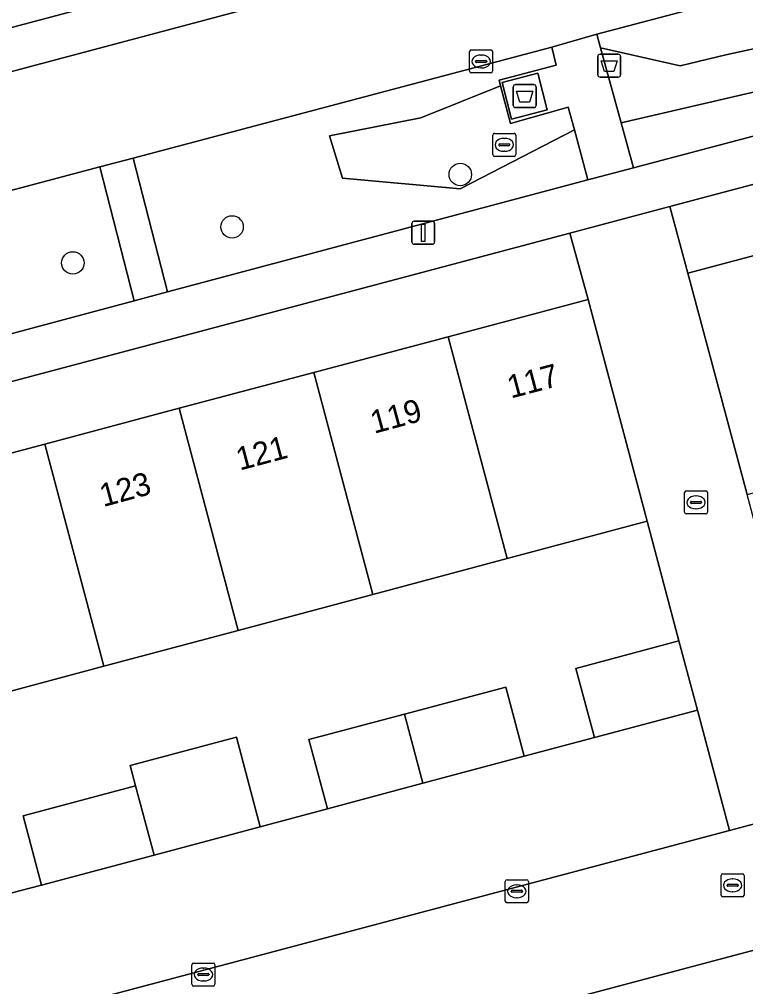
# Model space of a CAD drawing. Extents: x 162542 to 163147, y 380779 to 381521.
# Drawn here: x 162829.86 to 162861.43, y 381110.8 to 381152.86 of the extents above; entities that cross this region are included whole.
import ezdxf

# ---------------------------------------------------------------- set-up
doc = ezdxf.new("R2010")
doc.units = 0
for name, color, linetype in [('IMGEO_Afval_apart_plaats', 7, 'Continuous'), ('IMGEO_Afvalbak', 7, 'Continuous'), ('IMGEO_Boom', 7, 'Continuous'), ('IMGEO_Erf', 7, 'Continuous'), ('IMGEO_Groenvoorziening', 7, 'Continuous'), ('IMGEO_Kolk', 7, 'Continuous'), ('IMGEO_Lichtmast', 7, 'Continuous'), ('IMGEO_Muur', 7, 'Continuous'), ('IMGEO_Pand', 7, 'Continuous'), ('IMGEO_Pand_nummerreeks', 7, 'Continuous'), ('IMGEO_Parkeervlak_open', 7, 'Continuous'), ('IMGEO_Rijbaan_lokaal_open', 7, 'Continuous'), ('IMGEO_Rioolput', 7, 'Continuous'), ('IMGEO_Voetpad_gesloten', 7, 'Continuous'), ('IMGEO_Voetpad_open', 7, 'Continuous')]:
    doc.layers.add(name, color=color, linetype=linetype)

msp = doc.modelspace()

# ---------------------------------------------------------------- linework, layer by layer
at = {"layer": 'IMGEO_Afval_apart_plaats'}
for p, q in [((162851.333, 381149.125), (162851.333, 381149.925)), ((162851.333, 381149.925), (162851.333, 381149.125)), ((162851.433, 381150.025), (162852.223, 381150.025)), ((162852.223, 381150.025), (162851.433, 381150.025)), ((162852.323, 381149.925), (162852.323, 381149.125)), ((162852.323, 381149.125), (162852.323, 381149.925)), ((162852.223, 381149.025), (162851.433, 381149.025)), ((162851.433, 381149.025), (162852.223, 381149.025))]:
    msp.add_line(p, q, dxfattribs=at)
msp.add_lwpolyline([(162851.476, 381149.739), (162852.18, 381149.739), (162852.031, 381149.269), (162851.625, 381149.269), (162851.476, 381149.739)], dxfattribs=at)
for centre, start, end in [((162851.433, 381149.925), 90, 180), ((162851.433, 381149.925), 90, 180), ((162852.223, 381149.925), 0, 90), ((162852.223, 381149.925), 360, 90), ((162851.433, 381149.125), 180, 270), ((162851.433, 381149.125), 180, 270), ((162852.223, 381149.125), 270, 0), ((162852.223, 381149.125), 270, 0)]:
    msp.add_arc(centre, 0.1, start, end, dxfattribs=at)
at = {"layer": 'IMGEO_Afvalbak'}
for p, q in [((162855.006, 381150.45), (162855.006, 381151.25)), ((162855.006, 381151.25), (162855.006, 381150.45)), ((162855.106, 381151.35), (162855.896, 381151.35)), ((162855.896, 381151.35), (162855.106, 381151.35)), ((162855.996, 381151.25), (162855.996, 381150.45)), ((162855.996, 381150.45), (162855.996, 381151.25)), ((162855.896, 381150.35), (162855.106, 381150.35)), ((162855.106, 381150.35), (162855.896, 381150.35))]:
    msp.add_line(p, q, dxfattribs=at)
msp.add_lwpolyline([(162855.149, 381151.064), (162855.853, 381151.064), (162855.704, 381150.594), (162855.298, 381150.594), (162855.149, 381151.064)], dxfattribs=at)
for centre, start, end in [((162855.106, 381151.25), 90, 180), ((162855.106, 381151.25), 90, 180), ((162855.896, 381151.25), 0, 90), ((162855.896, 381151.25), 360, 90), ((162855.106, 381150.45), 180, 270), ((162855.106, 381150.45), 180, 270), ((162855.896, 381150.45), 270, 0), ((162855.896, 381150.45), 270, 0)]:
    msp.add_arc(centre, 0.1, start, end, dxfattribs=at)
at = {"layer": 'IMGEO_Boom'}
for centre in [(162849.03, 381146.117), (162839.107, 381143.836), (162832.187, 381142.27)]:
    msp.add_circle(centre, 0.489, dxfattribs=at)
at = {"layer": 'IMGEO_Erf'}
msp.add_lwpolyline([(162828.954, 381114.718), (162829.869, 381114.962), (162830.825, 381115.217), (162830.021, 381118.231), (162834.913, 381119.537), (162834.68, 381120.413), (162839.296, 381121.641), (162840.329, 381117.753), (162843.252, 381118.534), (162842.449, 381121.547), (162846.604, 381122.654), (162851.006, 381123.825), (162851.806, 381120.816), (162854.859, 381121.631), (162854.053, 381124.639), (162858.533, 381125.84), (162857.156, 381131.038), (162851.067, 381129.413), (162845.222, 381127.852), (162839.378, 381126.292), (162833.532, 381124.732), (162827.687, 381123.171)], dxfattribs=at)
at = {"layer": 'IMGEO_Groenvoorziening'}
for points in [[(162873.192, 381157.033), (162854.959, 381152.215), (162855.121, 381151.63), (162858.584, 381150.843), (162860.575, 381151.323), (162862.708, 381151.781), (162863.421, 381151.008), (162863.083, 381150.009), (162856.023, 381148.37), (162856.566, 381146.408), (162874.69, 381151.205)], [(162850.779, 381149.971), (162850.713, 381150.223), (162853.196, 381150.874), (162853.012, 381151.656), (162834.806, 381146.828), (162836.301, 381141.008), (162854.578, 381145.881), (162853.992, 381148.056), (162849.02, 381145.493), (162843.909, 381145.959), (162843.343, 381147.801), (162847.316, 381148.586)], [(162855.121, 381151.63), (162856.023, 381148.37), (162863.083, 381150.009), (162863.421, 381151.008), (162862.708, 381151.781), (162860.575, 381151.323), (162858.584, 381150.843)], [(162853.992, 381148.056), (162853.726, 381149.042), (162851.208, 381148.342), (162850.779, 381149.971), (162847.316, 381148.586), (162843.343, 381147.801), (162843.909, 381145.959), (162849.02, 381145.493)], [(162823.259, 381143.767), (162824.718, 381137.919), (162827.907, 381138.769), (162834.855, 381140.622), (162833.356, 381146.444)]]:
    msp.add_lwpolyline(points, close=True, dxfattribs=at)
at = {"layer": 'IMGEO_Kolk'}
for p, q in [((162849.509, 381151.533), (162850.361, 381151.533)), ((162849.434, 381150.607), (162849.434, 381151.459)), ((162849.922, 381151.313), (162849.947, 381151.313)), ((162850.435, 381151.459), (162850.435, 381150.607)), ((162849.693, 381151.027), (162849.693, 381151.039)), ((162850.131, 381150.99), (162849.733, 381150.99)), ((162849.736, 381151.076), (162850.134, 381151.076)), ((162849.945, 381150.753), (162849.92, 381150.753)), ((162850.177, 381151.039), (162850.177, 381151.027)), ((162850.361, 381150.533), (162849.509, 381150.533)), ((162858.777, 381131.431), (162858.777, 381132.283)), ((162858.852, 381132.357), (162859.704, 381132.357)), ((162859.778, 381132.283), (162859.778, 381131.431)), ((162859.036, 381131.851), (162859.036, 381131.863)), ((162859.474, 381131.814), (162859.076, 381131.814)), ((162859.079, 381131.9), (162859.477, 381131.9)), ((162859.265, 381132.137), (162859.29, 381132.137)), ((162859.52, 381131.863), (162859.52, 381131.851)), ((162859.704, 381131.357), (162858.852, 381131.357)), ((162859.288, 381131.577), (162859.263, 381131.577)), ((162850.987, 381114.519), (162850.987, 381115.371)), ((162851.062, 381115.445), (162851.914, 381115.445)), ((162851.988, 381115.371), (162851.988, 381114.519)), ((162851.246, 381114.939), (162851.246, 381114.951)), ((162851.289, 381114.988), (162851.687, 381114.988)), ((162851.475, 381115.225), (162851.5, 381115.225)), ((162851.73, 381114.951), (162851.73, 381114.939)), ((162851.684, 381114.902), (162851.286, 381114.902)), ((162851.498, 381114.665), (162851.473, 381114.665)), ((162851.914, 381114.445), (162851.062, 381114.445)), ((162837.363, 381110.899), (162837.363, 381111.751)), ((162837.438, 381111.825), (162838.29, 381111.825)), ((162837.851, 381111.605), (162837.876, 381111.605)), ((162838.364, 381111.751), (162838.364, 381110.899)), ((162837.622, 381111.319), (162837.622, 381111.331)), ((162838.06, 381111.282), (162837.662, 381111.282)), ((162837.665, 381111.368), (162838.063, 381111.368)), ((162838.106, 381111.331), (162838.106, 381111.319)), ((162838.29, 381110.825), (162837.438, 381110.825)), ((162837.874, 381111.045), (162837.849, 381111.045))]:
    msp.add_line(p, q, dxfattribs=at)
for points in [[(162849.509, 381151.533), (162850.361, 381151.533)], [(162849.434, 381150.607), (162849.434, 381151.459)], [(162850.435, 381151.459), (162850.435, 381150.607)], [(162850.361, 381150.533), (162849.509, 381150.533)], [(162858.777, 381131.431), (162858.777, 381132.283)], [(162858.852, 381132.357), (162859.704, 381132.357)], [(162859.778, 381132.283), (162859.778, 381131.431)], [(162859.704, 381131.357), (162858.852, 381131.357)], [(162850.987, 381114.519), (162850.987, 381115.371)], [(162851.062, 381115.445), (162851.914, 381115.445)], [(162851.988, 381115.371), (162851.988, 381114.519)], [(162851.914, 381114.445), (162851.062, 381114.445)], [(162837.363, 381110.899), (162837.363, 381111.751)], [(162837.438, 381111.825), (162838.29, 381111.825)], [(162838.364, 381111.751), (162838.364, 381110.899)], [(162838.29, 381110.825), (162837.438, 381110.825)]]:
    msp.add_lwpolyline(points, dxfattribs=at)
for centre, radius, start, end in [((162849.511, 381151.457), 0.0765, 91.552, 178.448), ((162849.511, 381151.457), 0.0765, 91.552, 178.448), ((162850.359, 381151.457), 0.0765, 1.552, 88.448), ((162850.359, 381151.457), 0.0765, 1.552, 88.448), ((162849.733, 381151.036), 0.0403, 85.8775, 175.7526), ((162849.73, 381151.026), 0.0366, 178.938, 274.7102), ((162850.134, 381151.033), 0.043, 264.8664, 352.4533), ((162850.138, 381151.038), 0.0386, 1.7309, 96.639), ((162849.511, 381150.609), 0.0765, 181.552, 268.448), ((162849.511, 381150.609), 0.0765, 181.552, 268.448), ((162850.359, 381150.609), 0.0765, 271.552, 358.448), ((162850.359, 381150.609), 0.0765, 271.552, 358.448), ((162858.854, 381132.281), 0.0765, 91.552, 178.448), ((162858.854, 381132.281), 0.0765, 91.552, 178.448), ((162859.702, 381132.281), 0.0765, 1.552, 88.448), ((162859.702, 381132.281), 0.0765, 1.552, 88.448), ((162859.076, 381131.86), 0.0403, 85.8775, 175.7526), ((162859.073, 381131.85), 0.0366, 178.938, 274.7102), ((162859.477, 381131.857), 0.043, 264.8664, 352.4533), ((162859.481, 381131.862), 0.0386, 1.7309, 96.639), ((162858.854, 381131.433), 0.0765, 181.552, 268.448), ((162858.854, 381131.433), 0.0765, 181.552, 268.448), ((162859.702, 381131.433), 0.0765, 271.552, 358.448), ((162859.702, 381131.433), 0.0765, 271.552, 358.448), ((162851.064, 381115.369), 0.0765, 91.552, 178.448), ((162851.064, 381115.369), 0.0765, 91.552, 178.448), ((162851.912, 381115.369), 0.0765, 1.552, 88.448), ((162851.912, 381115.369), 0.0765, 1.552, 88.448), ((162851.286, 381114.948), 0.0403, 85.8775, 175.7526), ((162851.283, 381114.938), 0.0366, 178.938, 274.7102), ((162851.687, 381114.945), 0.043, 264.8664, 352.4533), ((162851.691, 381114.95), 0.0386, 1.7309, 96.639), ((162851.064, 381114.521), 0.0765, 181.552, 268.448), ((162851.064, 381114.521), 0.0765, 181.552, 268.448), ((162851.912, 381114.521), 0.0765, 271.552, 358.448), ((162851.912, 381114.521), 0.0765, 271.552, 358.448), ((162837.44, 381111.749), 0.0765, 91.552, 178.448), ((162837.44, 381111.749), 0.0765, 91.552, 178.448), ((162838.288, 381111.749), 0.0765, 1.552, 88.448), ((162838.288, 381111.749), 0.0765, 1.552, 88.448), ((162837.662, 381111.328), 0.0403, 85.8775, 175.7526), ((162837.659, 381111.318), 0.0366, 178.938, 274.7102), ((162838.063, 381111.325), 0.043, 264.8664, 352.4533), ((162838.067, 381111.33), 0.0386, 1.7309, 96.639), ((162837.44, 381110.901), 0.0765, 181.552, 268.448), ((162837.44, 381110.901), 0.0765, 181.552, 268.448), ((162838.288, 381110.901), 0.0765, 271.552, 358.448), ((162838.288, 381110.901), 0.0765, 271.552, 358.448)]:
    msp.add_arc(centre, radius, start, end, dxfattribs=at)
for centre, major_axis, ratio, start_param, end_param in [((162849.921, 381151.033), (-0.387, 0.002), 0.722429, 4.712389, 7.853982), ((162849.946, 381151.033), (-0.39, 0.002), 0.717154, 1.570796, 4.712389), ((162859.264, 381131.857), (-0.387, 0.002), 0.722429, 4.712389, 7.853982), ((162859.289, 381131.857), (-0.39, 0.002), 0.717154, 1.570796, 4.712389), ((162851.474, 381114.945), (-0.387, 0.002), 0.722429, 4.712389, 7.853982), ((162851.499, 381114.945), (-0.39, 0.002), 0.717154, 1.570796, 4.712389), ((162837.85, 381111.325), (-0.387, 0.002), 0.722429, 4.712389, 7.853982), ((162837.875, 381111.325), (-0.39, 0.002), 0.717154, 1.570796, 4.712389)]:
    msp.add_ellipse(centre, major_axis=major_axis, ratio=ratio, start_param=start_param, end_param=end_param, dxfattribs=at)
at = {"layer": 'IMGEO_Lichtmast'}
for p, q in [((162846.925, 381143.181), (162846.925, 381143.981)), ((162846.925, 381143.981), (162846.925, 381143.181)), ((162847.025, 381144.081), (162847.815, 381144.081)), ((162847.815, 381144.081), (162847.025, 381144.081)), ((162847.915, 381143.981), (162847.915, 381143.181)), ((162847.915, 381143.181), (162847.915, 381143.981)), ((162847.815, 381143.081), (162847.025, 381143.081)), ((162847.025, 381143.081), (162847.815, 381143.081))]:
    msp.add_line(p, q, dxfattribs=at)
msp.add_lwpolyline([(162847.345, 381143.956), (162847.495, 381143.956), (162847.495, 381143.206), (162847.345, 381143.206), (162847.345, 381143.956)], dxfattribs=at)
for centre, start, end in [((162847.025, 381143.981), 90, 180), ((162847.025, 381143.981), 90, 180), ((162847.815, 381143.981), 0, 90), ((162847.815, 381143.981), 360, 90), ((162847.025, 381143.181), 180, 270), ((162847.025, 381143.181), 180, 270), ((162847.815, 381143.181), 270, 0), ((162847.815, 381143.181), 270, 0)]:
    msp.add_arc(centre, 0.1, start, end, dxfattribs=at)
at = {"layer": 'IMGEO_Muur'}
msp.add_lwpolyline([(162857.156, 381131.038), (162858.533, 381125.84)], dxfattribs=at)
at = {"layer": 'IMGEO_Pand'}
for points in [[(162865.183, 381143.493), (162858.926, 381141.83), (162861.5, 381132.198), (162867.747, 381133.851)], [(162851.067, 381129.413), (162857.156, 381131.038), (162854.582, 381140.682), (162848.502, 381139.062)], [(162845.222, 381127.852), (162851.067, 381129.413), (162848.502, 381139.062), (162842.656, 381137.506)], [(162845.222, 381127.852), (162842.656, 381137.506), (162836.811, 381135.949), (162839.378, 381126.292)], [(162830.964, 381134.392), (162833.532, 381124.732), (162839.378, 381126.292), (162836.811, 381135.949)], [(162825.118, 381132.835), (162827.687, 381123.171), (162833.532, 381124.732), (162830.964, 381134.392)], [(162858.533, 381125.84), (162854.053, 381124.639), (162854.859, 381121.631), (162859.337, 381122.826)], [(162851.006, 381123.825), (162846.604, 381122.654), (162847.405, 381119.642), (162851.806, 381120.816)], [(162846.604, 381122.654), (162842.449, 381121.547), (162843.252, 381118.534), (162847.405, 381119.642)], [(162834.913, 381119.537), (162835.715, 381116.522), (162840.329, 381117.753), (162839.296, 381121.641), (162834.68, 381120.413)], [(162834.913, 381119.537), (162830.021, 381118.231), (162830.825, 381115.217), (162835.715, 381116.522)]]:
    msp.add_lwpolyline(points, close=True, dxfattribs=at)
at = {"layer": 'IMGEO_Parkeervlak_open'}
for points in [[(162750.234, 381131.33), (162666.499, 381109.073), (162666.934, 381107.34), (162774.201, 381135.871), (162796.063, 381141.696), (162882.877, 381164.808), (162901.876, 381169.92), (162904.167, 381170.544), (162903.648, 381172.331), (162882.303, 381166.521), (162850.91, 381158.201), (162843.113, 381156.134), (162825.633, 381151.487), (162819.826, 381149.913), (162790.747, 381142.166), (162781.519, 381139.707), (162755.957, 381132.897)], [(162860.735, 381117.589), (162859.337, 381122.826), (162854.859, 381121.631), (162851.806, 381120.816), (162847.405, 381119.642), (162843.252, 381118.534), (162840.329, 381117.753), (162835.715, 381116.522), (162830.825, 381115.217), (162829.869, 381114.962), (162828.954, 381114.718), (162824.567, 381113.548), (162825.307, 381110.691), (162824.579, 381110.496), (162813.513, 381107.551), (162801.688, 381104.403), (162802.147, 381102.023)]]:
    msp.add_lwpolyline(points, close=True, dxfattribs=at)
at = {"layer": 'IMGEO_Rijbaan_lokaal_open'}
for points in [[(162854.959, 381152.215), (162873.192, 381157.033), (162874.356, 381157.34), (162885.803, 381160.365), (162885.815, 381160.368), (162895.148, 381162.891), (162896.342, 381163.214), (162903.106, 381165.042), (162901.876, 381169.92), (162882.877, 381164.808), (162796.063, 381141.696), (162797.369, 381136.894), (162804.174, 381138.709), (162806.152, 381139.231), (162816.765, 381142.045), (162822.073, 381143.452), (162823.259, 381143.767), (162833.356, 381146.444), (162834.806, 381146.828), (162853.012, 381151.656)], [(162901.595, 381122.971), (162901.741, 381122.714), (162904.267, 381123.387), (162904.26, 381123.431), (162912.087, 381125.607), (162919.026, 381127.451), (162917.722, 381132.729), (162865.087, 381118.745), (162860.735, 381117.589), (162802.147, 381102.023), (162803.453, 381096.881), (162812.174, 381099.193), (162820.968, 381101.532), (162820.992, 381101.538)]]:
    msp.add_lwpolyline(points, close=True, dxfattribs=at)
at = {"layer": 'IMGEO_Rioolput'}
for p, q in [((162850.442, 381146.981), (162850.442, 381147.833)), ((162850.517, 381147.907), (162851.369, 381147.907)), ((162851.443, 381147.833), (162851.443, 381146.981)), ((162850.701, 381147.401), (162850.701, 381147.413)), ((162851.139, 381147.364), (162850.741, 381147.364)), ((162850.744, 381147.45), (162851.142, 381147.45)), ((162850.93, 381147.687), (162850.955, 381147.687)), ((162851.185, 381147.413), (162851.185, 381147.401)), ((162851.369, 381146.907), (162850.517, 381146.907)), ((162850.953, 381147.127), (162850.928, 381147.127)), ((162860.368, 381114.779), (162860.368, 381115.631)), ((162860.443, 381115.705), (162861.295, 381115.705)), ((162860.856, 381115.485), (162860.881, 381115.485)), ((162861.369, 381115.631), (162861.369, 381114.779)), ((162860.627, 381115.199), (162860.627, 381115.211)), ((162861.065, 381115.162), (162860.667, 381115.162)), ((162860.67, 381115.248), (162861.068, 381115.248)), ((162860.879, 381114.925), (162860.854, 381114.925)), ((162861.111, 381115.211), (162861.111, 381115.199)), ((162861.295, 381114.705), (162860.443, 381114.705))]:
    msp.add_line(p, q, dxfattribs=at)
for points in [[(162850.442, 381146.981), (162850.442, 381147.833)], [(162850.517, 381147.907), (162851.369, 381147.907)], [(162851.443, 381147.833), (162851.443, 381146.981)], [(162851.369, 381146.907), (162850.517, 381146.907)], [(162860.368, 381114.779), (162860.368, 381115.631)], [(162860.443, 381115.705), (162861.295, 381115.705)], [(162861.369, 381115.631), (162861.369, 381114.779)], [(162861.295, 381114.705), (162860.443, 381114.705)]]:
    msp.add_lwpolyline(points, dxfattribs=at)
for centre, radius, start, end in [((162850.519, 381147.831), 0.0765, 91.552, 178.448), ((162850.519, 381147.831), 0.0765, 91.552, 178.448), ((162851.367, 381147.831), 0.0765, 1.552, 88.448), ((162851.367, 381147.831), 0.0765, 1.552, 88.448), ((162850.741, 381147.41), 0.0403, 85.8775, 175.7526), ((162850.738, 381147.4), 0.0366, 178.938, 274.7102), ((162851.142, 381147.407), 0.043, 264.8664, 352.4533), ((162851.146, 381147.412), 0.0386, 1.7309, 96.639), ((162850.519, 381146.983), 0.0765, 181.552, 268.448), ((162850.519, 381146.983), 0.0765, 181.552, 268.448), ((162851.367, 381146.983), 0.0765, 271.552, 358.448), ((162851.367, 381146.983), 0.0765, 271.552, 358.448), ((162860.445, 381115.629), 0.0765, 91.552, 178.448), ((162860.445, 381115.629), 0.0765, 91.552, 178.448), ((162861.293, 381115.629), 0.0765, 1.552, 88.448), ((162861.293, 381115.629), 0.0765, 1.552, 88.448), ((162860.667, 381115.208), 0.0403, 85.8775, 175.7526), ((162860.664, 381115.198), 0.0366, 178.938, 274.7102), ((162861.068, 381115.205), 0.043, 264.8664, 352.4533), ((162861.072, 381115.21), 0.0386, 1.7309, 96.639), ((162860.445, 381114.781), 0.0765, 181.552, 268.448), ((162860.445, 381114.781), 0.0765, 181.552, 268.448), ((162861.293, 381114.781), 0.0765, 271.552, 358.448), ((162861.293, 381114.781), 0.0765, 271.552, 358.448)]:
    msp.add_arc(centre, radius, start, end, dxfattribs=at)
for centre, major_axis, ratio, start_param, end_param in [((162850.929, 381147.407), (-0.387, 0.002), 0.722429, 4.712389, 7.853982), ((162850.954, 381147.407), (-0.39, 0.002), 0.717154, 1.570796, 4.712389), ((162860.855, 381115.205), (-0.387, 0.002), 0.722429, 4.712389, 7.853982), ((162860.88, 381115.205), (-0.39, 0.002), 0.717154, 1.570796, 4.712389)]:
    msp.add_ellipse(centre, major_axis=major_axis, ratio=ratio, start_param=start_param, end_param=end_param, dxfattribs=at)
at = {"layer": 'IMGEO_Voetpad_gesloten'}
msp.add_lwpolyline([(162852.394, 381150.52), (162850.849, 381150.118), (162851.262, 381148.529), (162852.807, 381148.931)], close=True, dxfattribs=at)
at = {"layer": 'IMGEO_Voetpad_open'}
for points in [[(162843.113, 381156.134), (162843.017, 381156.539), (162846.75, 381157.541), (162846.285, 381159.202), (162842.87, 381158.314), (162839.945, 381157.499), (162825.346, 381153.616), (162818.917, 381151.907), (162804.298, 381148.019), (162802.412, 381147.484), (162800.448, 381146.979), (162790.159, 381144.372), (162790.747, 381142.166), (162819.826, 381149.913), (162819.71, 381150.365), (162825.535, 381151.911), (162825.633, 381151.487)], [(162858.926, 381141.83), (162865.183, 381143.493), (162870.982, 381145.035), (162876.781, 381146.577), (162882.579, 381148.119), (162888.27, 381149.632), (162887.505, 381152.528), (162858.133, 381144.726)], [(162856.023, 381148.37), (162855.121, 381151.63), (162854.959, 381152.215), (162853.012, 381151.656), (162853.196, 381150.874), (162850.713, 381150.223), (162850.779, 381149.971), (162851.208, 381148.342), (162853.726, 381149.042), (162853.992, 381148.056), (162854.578, 381145.881), (162856.566, 381146.408)], [(162851.262, 381148.529), (162850.849, 381150.118), (162852.394, 381150.52), (162852.807, 381148.931)], [(162836.301, 381141.008), (162834.806, 381146.828), (162833.356, 381146.444), (162834.855, 381140.622)], [(162858.926, 381141.83), (162858.133, 381144.726), (162853.786, 381143.563), (162854.582, 381140.682), (162857.156, 381131.038), (162858.533, 381125.84), (162859.337, 381122.826), (162860.735, 381117.589), (162865.087, 381118.745), (162863.692, 381123.971), (162862.89, 381126.986), (162861.5, 381132.198)], [(162818.672, 381134.227), (162819.465, 381131.329), (162825.118, 381132.835), (162830.964, 381134.392), (162836.811, 381135.949), (162842.656, 381137.506), (162848.502, 381139.062), (162854.582, 381140.682), (162853.786, 381143.563)]]:
    msp.add_lwpolyline(points, close=True, dxfattribs=at)
for points in [[(162887.685, 381154.645), (162875.889, 381151.523), (162874.69, 381151.205), (162856.566, 381146.408), (162854.578, 381145.881), (162836.301, 381141.008), (162834.855, 381140.622), (162827.907, 381138.769), (162824.718, 381137.919), (162823.599, 381137.62), (162818.27, 381136.199), (162807.632, 381133.362), (162805.687, 381132.844), (162798.503, 381130.928)], [(162801.2, 381129.568), (162807.214, 381131.172), (162813.229, 381132.776), (162818.672, 381134.227), (162853.786, 381143.563), (162858.133, 381144.726), (162887.505, 381152.528), (162892.949, 381153.986)], [(162905.367, 381109.1), (162904.158, 381113.641), (162902.948, 381118.181), (162901.741, 381122.714), (162901.595, 381122.971), (162820.992, 381101.538)]]:
    msp.add_lwpolyline(points, dxfattribs=at)

# ---------------------------------------------------------------- texts
at = {"layer": 'IMGEO_Pand_nummerreeks'}
for s, rotation, p in [('117', 14.7796, (162851.224, 381136.37)), ('119', 15.0779, (162845.28, 381134.838)), ('121', 14.9314, (162839.438, 381133.237)), ('123', 15.2335, (162833.508, 381131.652))]:
    msp.add_text(s, height=1, rotation=rotation, dxfattribs=at).set_placement(p)

doc.saveas('drawing.dxf')
